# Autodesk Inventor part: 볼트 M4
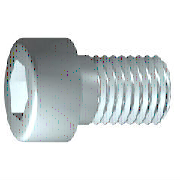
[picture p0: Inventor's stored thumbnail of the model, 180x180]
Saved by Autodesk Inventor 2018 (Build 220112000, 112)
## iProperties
IsCustomPart: 0
Created: 2012-02
Part Number: 볼트 M4
Material: 스테인리스강
Description: 6각 소켓 머리 캡 나사
Document SubType Name: Modeling
Standard: ISO 4762
Designer: mduedu
Standard Revision: Fourth edition 2004-03-01
Standards Organization: ISO
Language: ko-KR
Size Designation: M4 x 12
Categories: <MemberInstance><Categories><Category DisplayName="조임쇠" InternalName="e4da775c-781d-43d5-af7c-5136215cf5a6" Mnemonic="FSTN"><Category DisplayName="볼트" InternalN
Density: 7.75 g/cm^3
Appearance: 반광택
Author: mduedu
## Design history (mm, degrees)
sketch "스케치1"
  geometry: L1 (-1, 0)-(12, 0); L2 (12, 0)-(12, 2); L3 (12, 2)-(1.75, 2); L4 (1.75, 2)-(1.32, 2); L5 (1.32, 2)-(0, 2); L6 (0, 2)-(0, 3.5); L7 (0, 3.5)-(-4, 3.5); L8 (-4, 3.5)-(-4, 1.732); L9 (-4, 1.732)-(-2, 1.732); L10 (-2, 1.732)-(-1, 0); L11 (-7.2, 0)-(15.2, 0) reference; L12 (0, -0.7)-(0, 4.2) reference; L13 (1.75, 2)-(0, 2)
  constraints: 22 end point, 6 parallel, 2 collinear, 2 perpendicular, 1 horizontal, 1 point on line
  dimensions: "d1" = 10.25 distance from line of L3.end L2 (= GEL); "d2" = 0.42952 distance of L4.end L3.end (computed from GAL); "d3" = 4 distance between parallel lines of L8 L6 (= KOH); "d4" = 2 distance of L8.end L9.end (= INTI); "d5" = 60 deg angle of L10 L1; "d6" = 4 diameter of L3 L1 (= GD); "d7" = 4 diameter of L5 L1 (= BDM); "d8" = 3.4641 diameter of L9 L1 (= 1.1547 x SW); "d9" = 7 diameter of L7 L1 (= KOD); "d26" = 12 distance between parallel lines of L12 L2 (= NLG)
revolve "본체" sketch "스케치1" stored, may be unused: angle "d10" = 90 deg
sketch "스케치2"
  geometry: L1 (0, -4.9)-(0, 4.9) reference; L2 (-4.9, 0)-(4.9, 0) reference; L3 (1.732, 0)-(0.866, -1.5); L4 (0.866, -1.5)-(-0.866, -1.5); L5 (-0.866, -1.5)-(-1.732, 0); L6 (-1.732, 0)-(-0.866, 1.5); L7 (-0.866, 1.5)-(0.866, 1.5); L8 (0.866, 1.5)-(1.732, 0); 2 further points
  constraints: 12 end point, 1 coincident, 1 horizontal alignment, 1 point on line, 12 other
extrude "슬롯" join sketch "스케치2" stored distance "d11" = 10; taper "d12" = 0 deg
workplane "Work Plane1"
fillet "Fillet2" dims "d30" = 0.1 (= R)
body "Solid1"
fillet "모깎기1" dims "d17" = 0.4 (= RR)
feature "스레드" dims "d13" = 10.25 (= GEL), "d14" = 0
chamfer "모따기1" distance "d15" = 0.42941 (= -0.5 x SPD + 0.5 x GD); stored, may be unused: second distance "d16" = 0.42941 (= GUL), angle "d27" = 45 deg
other parameters: "GD" = 4 [user parameter; used in 2 equation terms], "NLG" = 12 [user parameter; used in 1 equation term], "GEL" = 10.25 [user parameter; used in 2 equation terms], "KOD" = 7 [user parameter; used in 1 equation term], "KOH" = 4 [user parameter; used in 1 equation term], "INTI" = 2 [user parameter; used in 1 equation term], "GAL" = 0.42941 (= 0.61345 x PTC) [user parameter; used in 1 equation term], "GUL" = 0.42941 (= 0.61345 x PTC) [user parameter; used in 1 equation term], "BDM" = 4 (= NND) [user parameter; used in 1 equation term], "SW" = 3 [user parameter; used in 2 equation terms], "RR" = 0.4 [user parameter; used in 1 equation term], "SPD" = 3.14117 (= NND - 1.2269 x PTC) [user parameter; used in 1 equation term], "d19" = 0, "d28" = 0, "d29" = 0, "R" = 0.1 [user parameter; used in 1 equation term], "TOA" = 30 deg [user parameter], "GD1" = 3.14117 (= THREADDIA - 1.2269 x PTC) [user parameter], "THREADDIA" = 4 [user parameter; used in 1 equation term], "FAWI" = 45 deg [user parameter], "TPU" = 14.28571 (computed from PTC) [user parameter], "PTC" = 0.7 [user parameter; used in 5 equation terms], "NND" = 4 [user parameter; used in 2 equation terms], "E0" = 3.465 (= 1.155 x SW) [user parameter]
